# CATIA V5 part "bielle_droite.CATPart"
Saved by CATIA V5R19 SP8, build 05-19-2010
Part number: bielle_droite
Bounding box of the stored display mesh (mm): x 825 to 900, y -929.893 to -300.464, z 80.253 to 289.943
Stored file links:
  G:\EU_thinkMotion\CFAO_2010\MMS_groupe2\MMS_groupe2\OK\mmartini\mmartiniCFAO\bielle_droite.CATPart
  C:\Users\Mathieu Martini\Desktop\CFAO\Animation\CFAO.CATProduct
  G:\EU_thinkMotion\CFAO_2010\MMS_groupe2\MMS_groupe2\OK\mmartini\mmartiniCFAO\Squelette.CATPart
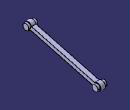
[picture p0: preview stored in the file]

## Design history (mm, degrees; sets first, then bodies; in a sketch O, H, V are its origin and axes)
External parameters (linked from other documents)
  External.diametre_verin = 120 mm
  External.diametre_canon = 150 mm
AxisSystem1: origin (0, 0, 0), X (1, 0, 0), Y (0, 1, 0), Z (0, 0, 1)
Set1
  Sketch1 on Plane1, origin (825, 0, 0), H (0, 1, 0), V (0, 0, 1)
    construction line L1 (-900, 475.8261) -> (-900, 148.4206)
    reference projected point E1 (-900, 150) from Line1
    arc A1 centre (-900, 260) radius 30 from (-871.0586, 267.899) to (-878.6885, 238.8855) ccw
    point P3 (-900, 260)
    reference projected point E2 (-900, 150) from Line1
    construction line L2 (-225.3499, 63.5264) -> (-426.6483, 152.9923)
    reference projected line E3 through (-74.2268, -167.0103) direction (0.9138, -0.4061) from Line2
    reference projected point E4 (-376.0481, 130.5033) from Point1
    point P6 (-330.3575, 110.1964)
    reference projected point E5 (-376.0481, 130.5033) from Point1
    axis line L3 (-330.3575, 110.1964) -> (-900, 260)
    point P7 (-900, 260)
    line L4 (-351.669, 131.3109) -> (-871.0586, 267.899)
    point P8 (-351.669, 131.3109)
    point P9 (-871.0586, 267.899)
    point P10 (-878.6885, 238.8855)
    point P11 (-359.2989, 102.2974)
    line L5 (-359.2989, 102.2974) -> (-878.6885, 238.8855)
    arc A2 centre (-330.3575, 110.1964) radius 30 from (-359.2989, 102.2974) to (-351.669, 131.3109) ccw
    circle A3 centre (-900, 260) radius 24
    point P12 (-914.304, 279.2716)
    circle A4 centre (-330.3575, 110.1964) radius 24
    radius A1 = 30 {= External.diametre_verin/ 4}
    distance P3 E2 = 110 {= External.diametre_canon *0.73333333}
    distance P6 E5 = 50 {= External.diametre_canon /3}
    distance L3 L4 = 15 {= External.diametre_canon /10}
    radius A3 = 24 {= External.diametre_verin /5}
    radius A2 = 30 {= External.diametre_canon /5}
    radius A4 = 24 {= External.diametre_verin /5}
    vertical: L1 V
    coincidence: L1 E1, P3 L1, E4 L2, P6 L2, L3 P3, P7 L1, A3 P12, P12 L4
    parallelism: L2 E3
    symmetry: P9 P10 L3, P8 P11 L3, L4 L5 L3
Set2
  Plane1 "Plan_jambe_droite_roue": linked copy from another document
  Line1 "axe_berceau_jambe": linked copy from another document
  Line2: linked copy from another document
  Point1: linked copy from another document
Body1 (main body)
  Pad1: profile Sketch1, direction (1, 0, 0), length 57.1429 {= External.diametre_verin /2.1}
  Sketch2 on start face of Pad1, origin (825, 0, 0), H (0, -1, 0), V (0, 0, 1)
  Pocket1: profile Sketch2, direction (1, 0, 0), length 20 {= External.diametre_verin /6}, deactivated
  Sketch3 on start face of Pad1, origin (825, 0, 0), H (0, -1, 0), V (0, 0, 1)
    projected arc E1 centre (900, 260) radius 30 from (878.6885, 238.8855) to (871.0586, 267.899) ccw from edge [start face of Pad1 | face of Pad1 from Sketch1.A1]
    projected line E2 (878.6885, 238.8855) -> (359.2989, 102.2974) from edge [start face of Pad1 | face of Pad1 from Sketch1.L5]
    projected arc E3 centre (330.3575, 110.1964) radius 30 from (351.669, 131.3109) to (359.2989, 102.2974) ccw from edge [start face of Pad1 | face of Pad1 from Sketch1.A2]
    projected line E4 (351.669, 131.3109) -> (871.0586, 267.899) from edge [start face of Pad1 | face of Pad1 from Sketch1.L4]
  Pocket2: profile Sketch3, direction (1, 0, 0), length 20 {= External.diametre_verin /6}
  Sketch4 on Plane1, origin (825, 0, 0), H (0, 1, 0), V (0, 0, 1)
    projected circle E1 centre (-900, 260) radius 24 from edge [end face of Pad1 | face of Pad1 from Sketch1.A3]
    projected circle E2 centre (-330.3575, 110.1964) radius 24 from edge [end face of Pocket2 | face of Pad1 from Sketch1.A4]
  Pad2: profile Sketch4, direction (1, 0, 0), length 75 {= External.diametre_canon /2}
